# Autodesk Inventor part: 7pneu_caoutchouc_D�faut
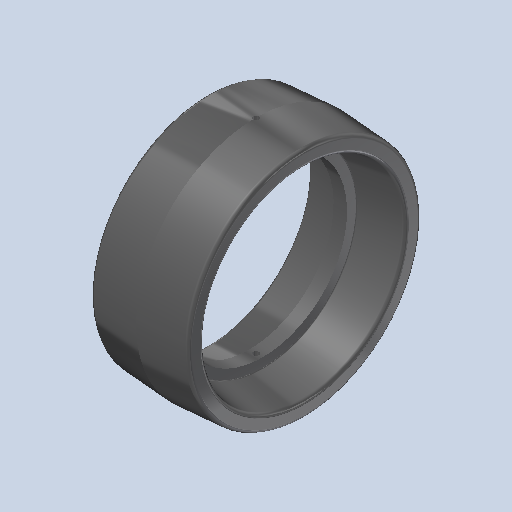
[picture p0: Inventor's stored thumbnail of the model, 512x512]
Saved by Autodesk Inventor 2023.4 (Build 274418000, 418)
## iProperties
Created: 2011-01
Part Number: 7pneu_caoutchouc_D�faut
Document SubType Name: Modeling
Designer: eric
Density: 1 g/cm^3
Mass: 1652.98 g
Surface Area: 1753.05 cm^2
Volume: 1652.98 cm^3
Material: Générique
Appearance: Caoutchouc - Noir - Version 1.1
Author: eric
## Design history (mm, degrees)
feature "Base1"
node "Corps solides"
node "Corps surfaciques"
node "Solide1"
